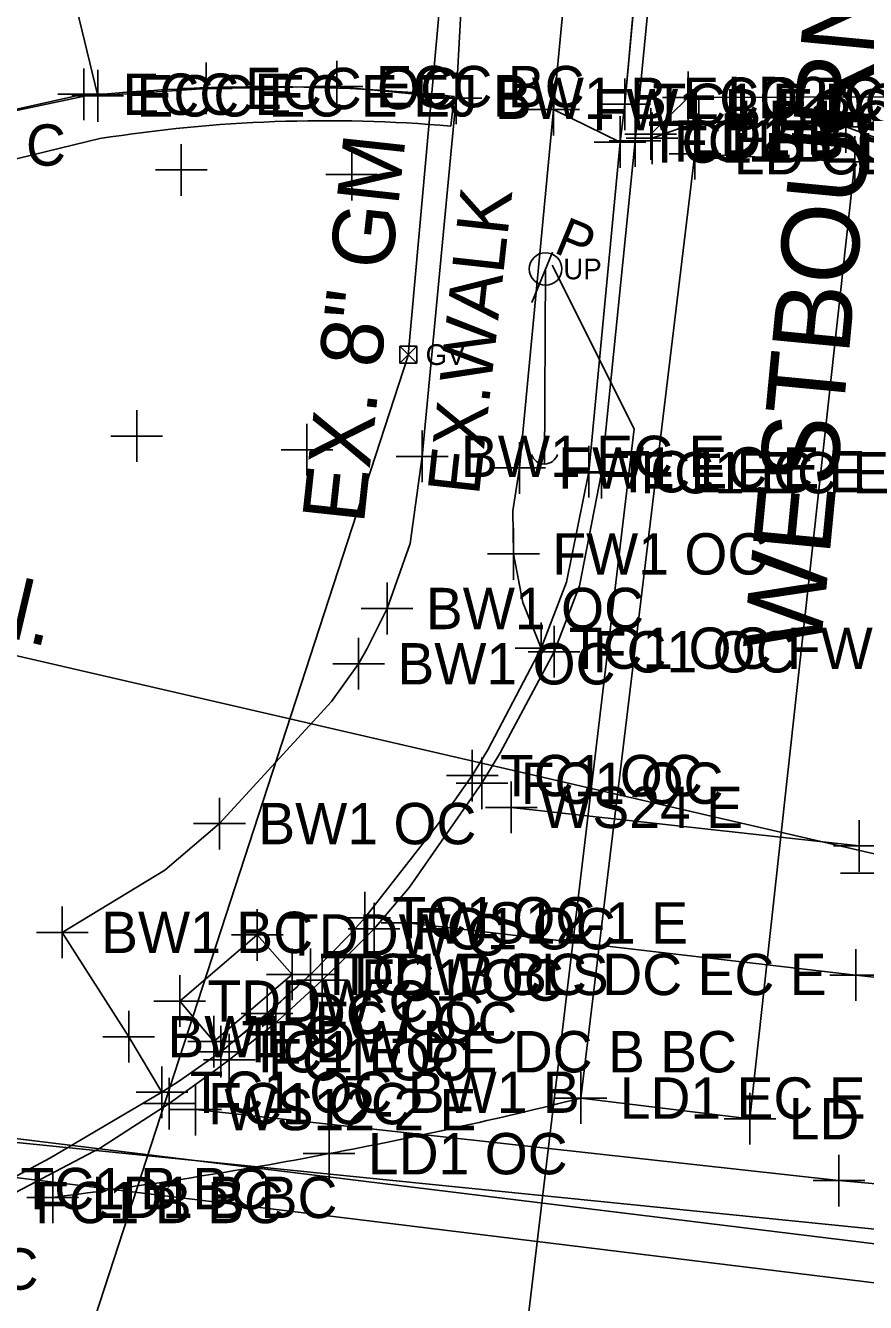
# Model space of a CAD drawing. Extents: x 1363693 to 1365209, y 422201 to 424153.
# Drawn here: x 1364205.52 to 1364238.02, y 423133.99 to 423183.39 of the extents above; entities that cross this region are included whole.
import ezdxf

# ---------------------------------------------------------------- set-up
doc = ezdxf.new("R2010")
doc.units = 0
for name, color, linetype in [('BASELINE-CL-RW', 7, 'Continuous'), ('DR_X_Cells', 7, 'Continuous'), ('DR_X_Storm_Sewer', 7, 'Continuous'), ('O-ALGN-TEXT-BASELINE-WERK-CL-RW', 7, 'Continuous'), ('OWNERS', 7, 'Continuous'), ('PM_X_Channelizing_Line', 7, 'Continuous'), ('PM_X_Crosswalk', 7, 'Continuous'), ('PM_X_Stop_Line', 7, 'Continuous'), ('PV_P_Curb_Ramp', 7, 'Continuous'), ('PV_X_Driveway', 7, 'Continuous'), ('PV_X_Joint', 7, 'Continuous'), ('RD_X_Misc_Items', 7, 'Continuous'), ('RD_X_Text', 7, 'Continuous'), ('SG_X_Wiring', 7, 'Continuous'), ('SV_X_Original_Ground', 7, 'Continuous'), ('SV_X_Shot_Marker', 7, 'Continuous'), ('UT_X_Gas', 7, 'Continuous'), ('UT_X_Gas_Cells', 7, 'Continuous'), ('UT_X_Gas_Text', 7, 'Continuous'), ('UT_X_Misc_Cells', 7, 'Continuous'), ('UT_X_Sanitary_Line', 7, 'Continuous'), ('UT_X_Sanitary_Text', 7, 'Continuous'), ('UT_X_Telecom', 7, 'Continuous'), ('UT_X_Unknown_Cells', 7, 'Continuous'), ('UT_X_Water', 7, 'Continuous')]:
    doc.layers.add(name, color=color, linetype=linetype)

msp = doc.modelspace()

# ---------------------------------------------------------------- linework, layer by layer
at = {"layer": 'BASELINE-CL-RW'}
msp.add_line((1364228.704, 423180.346), (1364229.658, 423190.76), dxfattribs=at)
for points in [[(1364228.704, 423180.346), (1364229.658, 423190.76), (1364230.073, 423195.223)], [(1364216.542, 423146.681), (1364218.062, 423148.207), (1364218.062, 423148.207), (1364218.647, 423148.872), (1364218.647, 423148.872), (1364221.458, 423152.474), (1364221.458, 423152.474), (1364222.808, 423154.374), (1364222.808, 423154.374), (1364223.41, 423155.375), (1364223.41, 423155.375), (1364225.467, 423159.303), (1364225.467, 423159.303), (1364226.448, 423161.853), (1364226.448, 423161.853), (1364227.316, 423166.131), (1364227.316, 423166.131), (1364228.525, 423178.884), (1364228.704, 423180.346)], [(1364213.077, 423143.69), (1364214.869, 423145.175), (1364214.869, 423145.175), (1364216.542, 423146.681), (1364216.542, 423146.681)], [(1364135.44, 423140.481), (1364146.794, 423139.321), (1364171.621, 423136.542), (1364184.9, 423135.157), (1364188.638, 423134.918), (1364188.638, 423134.918), (1364190.871, 423135.022), (1364190.871, 423135.022), (1364195.136, 423135.571), (1364195.136, 423135.571), (1364196.63, 423135.835), (1364196.63, 423135.835), (1364200.837, 423136.985), (1364200.837, 423136.985), (1364204.251, 423138.395), (1364204.251, 423138.395), (1364206.466, 423139.572), (1364206.466, 423139.572), (1364210.799, 423142.123), (1364210.799, 423142.123), (1364211.473, 423142.559), (1364211.473, 423142.559), (1364213.077, 423143.69), (1364213.077, 423143.69)]]:
    msp.add_lwpolyline(points, dxfattribs=at)
for start, end in [(310.84, 313.1458), (308.456, 310.84)]:
    msp.add_arc((1364178.289, 423187.494), 55.937, start, end, dxfattribs=at)
at = {"layer": 'DR_X_Cells'}
msp.add_line((1364225.598, 423166.428), (1364225.641, 423173.976), dxfattribs=at)
at = {"layer": 'DR_X_Storm_Sewer'}
for points in [[(1364396.704, 423122.381), (1364292.466, 423129.632), (1364116.736, 423151.168)], [(1364116.553, 423149.679), (1364292.322, 423128.138), (1364396.6, 423120.885)]]:
    msp.add_lwpolyline(points, dxfattribs=at)
at = {"layer": 'O-ALGN-TEXT-BASELINE-WERK-CL-RW'}
for points in [[(1364225.467, 423159.303), (1364224.762, 423161.077), (1364224.402, 423162.951), (1364224.402, 423162.951), (1364224.38, 423164.624), (1364224.634, 423166.277), (1364224.634, 423166.277), (1364225.951, 423180.141), (1364226.992, 423191.127), (1364227.411, 423195.297), (1364229.35, 423215.953), (1364230.018, 423223.684), (1364231.301, 423237.016), (1364231.57, 423240.495), (1364234.233, 423265.741), (1364235.185, 423277.97)], [(1364210.799, 423142.123), (1364209.512, 423144.272), (1364206.944, 423148.307), (1364210.908, 423150.717), (1364210.908, 423150.717), (1364213.026, 423152.516), (1364213.026, 423152.516), (1364217.363, 423157.247), (1364217.363, 423157.247), (1364218.408, 423158.7), (1364218.408, 423158.7), (1364218.736, 423159.297), (1364218.736, 423159.297), (1364219.511, 423160.839), (1364219.511, 423160.839), (1364220.402, 423163.353), (1364220.402, 423163.353), (1364220.868, 423166.723), (1364220.868, 423166.723), (1364222.181, 423180.581), (1364222.816, 423192.181)]]:
    msp.add_lwpolyline(points, dxfattribs=at)
at = {"layer": 'OWNERS'}
msp.add_line((1364225.951, 423180.141), (1364228.525, 423178.884), dxfattribs=at)
for points in [[(1364204.388, 423137.855), (1364208.419, 423139.966), (1364208.419, 423139.966), (1364211.084, 423141.681), (1364211.084, 423141.681), (1364212.881, 423142.988), (1364212.881, 423142.988), (1364213.403, 423143.382), (1364213.403, 423143.382), (1364214.699, 423144.404), (1364214.699, 423144.404), (1364215.206, 423144.822), (1364215.206, 423144.822), (1364215.65, 423145.214), (1364215.65, 423145.214), (1364217.001, 423146.462), (1364217.001, 423146.462), (1364217.732, 423147.164), (1364217.732, 423147.164), (1364219.01, 423148.449), (1364219.01, 423148.449), (1364220.38, 423150.056), (1364220.38, 423150.056), (1364223.181, 423154.079), (1364223.181, 423154.079), (1364223.885, 423155.254), (1364223.885, 423155.254), (1364225.97, 423159.163), (1364225.97, 423159.163), (1364226.957, 423161.717), (1364226.957, 423161.717), (1364227.81, 423166.094), (1364227.81, 423166.094), (1364229.109, 423178.929), (1364230.246, 423190.614)], [(1364222.181, 423180.581), (1364217.569, 423181.031), (1364212.513, 423180.959), (1364212.513, 423180.959), (1364208.315, 423180.675), (1364208.315, 423180.675)]]:
    msp.add_lwpolyline(points, dxfattribs=at)
at = {"layer": 'PM_X_Channelizing_Line'}
for p, q in [((1364237.781, 423151.651), (1364224.314, 423153.145)), ((1364237.643, 423146.658), (1364220.285, 423148.675)), ((1364248.32, 423145.383), (1364237.643, 423146.658)), ((1364236.991, 423138.704), (1364212.098, 423141.452)), ((1364247.655, 423137.745), (1364236.991, 423138.704))]:
    msp.add_line(p, q, dxfattribs=at)
at = {"layer": 'PM_X_Crosswalk'}
for p, q in [((1364237.643, 423146.658), (1364220.285, 423148.675)), ((1364248.32, 423145.383), (1364237.643, 423146.658)), ((1364236.991, 423138.704), (1364212.098, 423141.452)), ((1364247.655, 423137.745), (1364236.991, 423138.704))]:
    msp.add_line(p, q, dxfattribs=at)
at = {"layer": 'PM_X_Stop_Line'}
msp.add_line((1364237.781, 423151.651), (1364224.314, 423153.145), dxfattribs=at)
at = {"layer": 'PV_P_Curb_Ramp'}
for p, q in [((1364211.486, 423145.647), (1364214.488, 423148.21)), ((1364214.488, 423148.21), (1364215.839, 423146.681)), ((1364215.839, 423146.681), (1364212.802, 423144.082)), ((1364212.802, 423144.082), (1364211.486, 423145.647))]:
    msp.add_line(p, q, dxfattribs=at)
at = {"layer": 'PV_X_Driveway'}
msp.add_line((1364222.101, 423180.652), (1364221.975, 423179.502), dxfattribs=at)
for points in [[(1364222.181, 423180.581), (1364217.569, 423181.031), (1364212.513, 423180.959), (1364212.513, 423180.959), (1364208.315, 423180.675), (1364208.315, 423180.675)], [(1364155.876, 423180.336), (1364161.445, 423179.857), (1364175.888, 423178.423), (1364191.323, 423176.97), (1364200.019, 423179.021), (1364207.804, 423180.664)], [(1364184.767, 423177.698), (1364191.174, 423177.06), (1364198.926, 423178.771), (1364207.772, 423180.738)], [(1364208.394, 423179.018), (1364200.501, 423177.107), (1364191.136, 423174.993)]]:
    msp.add_lwpolyline(points, dxfattribs=at)
for centre, radius, start, end in [((1364214.895, 423111.882), 69.146, 84.01793, 95.88589), ((1364217.146, 423124.207), 55.505, 85.0094, 99.0727)]:
    msp.add_arc(centre, radius, start, end, dxfattribs=at)
at = {"layer": 'PV_X_Joint'}
msp.add_line((1364208.315, 423180.675), (1364206.439, 423188.424), dxfattribs=at)
at = {"layer": 'RD_X_Misc_Items'}
for p, q in [((1364211.486, 423145.647), (1364214.488, 423148.21)), ((1364214.488, 423148.21), (1364215.839, 423146.681)), ((1364215.839, 423146.681), (1364212.802, 423144.082)), ((1364212.802, 423144.082), (1364211.486, 423145.647))]:
    msp.add_line(p, q, dxfattribs=at)
at = {"layer": 'SG_X_Wiring'}
for p, q in [((1364229.712, 423179.192), (1364231.164, 423180.61)), ((1364231.164, 423180.61), (1364243.301, 423180.646)), ((1364229.761, 423179.031), (1364231.57, 423179.684)), ((1364231.57, 423179.684), (1364237.259, 423179.472)), ((1364237.259, 423179.472), (1364243.009, 423177.395)), ((1364231.42, 423178.435), (1364227.013, 423141.896)), ((1364237.607, 423178.115), (1364231.42, 423178.435)), ((1364233.552, 423141.095), (1364237.607, 423178.115)), ((1364227.013, 423141.896), (1364233.552, 423141.095))]:
    msp.add_line(p, q, dxfattribs=at)
for start, end in [(280.78464, 284.09861), (277.18978, 280.78464)]:
    msp.add_arc((1364184.979, 423309.257), 172.559, start, end, dxfattribs=at)
at = {"layer": 'SV_X_Original_Ground'}
for p, q in [((1364231.164, 423179.61), (1364231.164, 423181.61)), ((1364230.164, 423180.61), (1364232.164, 423180.61)), ((1364231.57, 423178.684), (1364231.57, 423180.684)), ((1364237.259, 423178.472), (1364237.259, 423180.472)), ((1364229.712, 423178.192), (1364229.712, 423180.192)), ((1364229.761, 423178.031), (1364229.761, 423180.031)), ((1364230.57, 423179.684), (1364232.57, 423179.684)), ((1364236.259, 423179.472), (1364238.259, 423179.472)), ((1364228.712, 423179.192), (1364230.712, 423179.192)), ((1364228.761, 423179.031), (1364230.761, 423179.031)), ((1364211.548, 423176.807), (1364211.548, 423178.807)), ((1364218.145, 423176.631), (1364218.145, 423178.631)), ((1364210.548, 423177.807), (1364212.548, 423177.807)), ((1364217.145, 423177.631), (1364219.145, 423177.631)), ((1364209.823, 423166.512), (1364209.823, 423168.512)), ((1364216.406, 423165.982), (1364216.406, 423167.982)), ((1364208.823, 423167.512), (1364210.823, 423167.512)), ((1364215.406, 423166.982), (1364217.406, 423166.982)), ((1364224.314, 423152.145), (1364224.314, 423154.145)), ((1364223.314, 423153.145), (1364225.314, 423153.145)), ((1364237.781, 423150.651), (1364237.781, 423152.651)), ((1364236.781, 423151.651), (1364238.781, 423151.651)), ((1364237.05, 423150.599), (1364239.05, 423150.599)), ((1364220.285, 423147.675), (1364220.285, 423149.675)), ((1364214.488, 423147.21), (1364214.488, 423149.21)), ((1364219.285, 423148.675), (1364221.285, 423148.675)), ((1364213.488, 423148.21), (1364215.488, 423148.21)), ((1364215.839, 423145.681), (1364215.839, 423147.681)), ((1364237.643, 423145.658), (1364237.643, 423147.658)), ((1364211.486, 423144.647), (1364211.486, 423146.647)), ((1364214.839, 423146.681), (1364216.839, 423146.681)), ((1364236.643, 423146.658), (1364238.643, 423146.658)), ((1364210.486, 423145.647), (1364212.486, 423145.647)), ((1364212.802, 423143.082), (1364212.802, 423145.082)), ((1364211.802, 423144.082), (1364213.802, 423144.082)), ((1364212.098, 423140.452), (1364212.098, 423142.452)), ((1364227.013, 423140.896), (1364227.013, 423142.896)), ((1364211.098, 423141.452), (1364213.098, 423141.452)), ((1364226.013, 423141.896), (1364228.013, 423141.896)), ((1364217.268, 423138.746), (1364217.268, 423140.746)), ((1364216.268, 423139.746), (1364218.268, 423139.746)), ((1364236.991, 423137.704), (1364236.991, 423139.704)), ((1364206.576, 423137.055), (1364206.576, 423139.055)), ((1364235.991, 423138.704), (1364237.991, 423138.704)), ((1364205.576, 423138.055), (1364207.576, 423138.055))]:
    msp.add_line(p, q, dxfattribs=at)
at = {"layer": 'SV_X_Shot_Marker'}
for p, q in [((1364212.513, 423179.959), (1364212.513, 423181.959)), ((1364217.569, 423180.031), (1364217.569, 423182.031)), ((1364207.772, 423179.738), (1364207.772, 423181.738)), ((1364208.315, 423179.675), (1364208.315, 423181.675)), ((1364222.181, 423179.581), (1364222.181, 423181.581)), ((1364211.513, 423180.959), (1364213.513, 423180.959)), ((1364216.569, 423181.031), (1364218.569, 423181.031)), ((1364225.951, 423179.141), (1364225.951, 423181.141)), ((1364228.704, 423179.346), (1364228.704, 423181.346)), ((1364206.772, 423180.738), (1364208.772, 423180.738)), ((1364207.315, 423180.675), (1364209.315, 423180.675)), ((1364221.181, 423180.581), (1364223.181, 423180.581)), ((1364224.951, 423180.141), (1364226.951, 423180.141)), ((1364227.704, 423180.346), (1364229.704, 423180.346)), ((1364228.525, 423177.884), (1364228.525, 423179.884)), ((1364229.109, 423177.929), (1364229.109, 423179.929)), ((1364231.42, 423177.435), (1364231.42, 423179.435)), ((1364237.607, 423177.115), (1364237.607, 423179.115)), ((1364227.525, 423178.884), (1364229.525, 423178.884)), ((1364228.109, 423178.929), (1364230.109, 423178.929)), ((1364230.42, 423178.435), (1364232.42, 423178.435)), ((1364236.607, 423178.115), (1364238.607, 423178.115)), ((1364220.868, 423165.723), (1364220.868, 423167.723)), ((1364224.634, 423165.277), (1364224.634, 423167.277)), ((1364227.316, 423165.131), (1364227.316, 423167.131)), ((1364219.868, 423166.723), (1364221.868, 423166.723)), ((1364227.81, 423165.094), (1364227.81, 423167.094)), ((1364223.634, 423166.277), (1364225.634, 423166.277)), ((1364226.316, 423166.131), (1364228.316, 423166.131)), ((1364226.81, 423166.094), (1364228.81, 423166.094)), ((1364224.402, 423161.951), (1364224.402, 423163.951)), ((1364223.402, 423162.951), (1364225.402, 423162.951)), ((1364219.511, 423159.839), (1364219.511, 423161.839)), ((1364218.511, 423160.839), (1364220.511, 423160.839)), ((1364225.467, 423158.303), (1364225.467, 423160.303)), ((1364225.97, 423158.163), (1364225.97, 423160.163)), ((1364218.408, 423157.7), (1364218.408, 423159.7)), ((1364224.467, 423159.303), (1364226.467, 423159.303)), ((1364224.97, 423159.163), (1364226.97, 423159.163)), ((1364217.408, 423158.7), (1364219.408, 423158.7)), ((1364222.808, 423153.374), (1364222.808, 423155.374)), ((1364223.181, 423153.079), (1364223.181, 423155.079)), ((1364221.808, 423154.374), (1364223.808, 423154.374)), ((1364222.181, 423154.079), (1364224.181, 423154.079)), ((1364213.026, 423151.516), (1364213.026, 423153.516)), ((1364212.026, 423152.516), (1364214.026, 423152.516)), ((1364218.647, 423147.872), (1364218.647, 423149.872)), ((1364219.01, 423147.449), (1364219.01, 423149.449)), ((1364206.944, 423147.307), (1364206.944, 423149.307)), ((1364217.647, 423148.872), (1364219.647, 423148.872)), ((1364218.01, 423148.449), (1364220.01, 423148.449)), ((1364205.944, 423148.307), (1364207.944, 423148.307)), ((1364216.542, 423145.681), (1364216.542, 423147.681)), ((1364217.001, 423145.462), (1364217.001, 423147.462)), ((1364215.542, 423146.681), (1364217.542, 423146.681)), ((1364216.001, 423146.462), (1364218.001, 423146.462)), ((1364214.869, 423144.175), (1364214.869, 423146.175)), ((1364215.206, 423143.822), (1364215.206, 423145.822)), ((1364209.512, 423143.272), (1364209.512, 423145.272)), ((1364213.869, 423145.175), (1364215.869, 423145.175)), ((1364213.077, 423142.69), (1364213.077, 423144.69)), ((1364214.206, 423144.822), (1364216.206, 423144.822)), ((1364208.512, 423144.272), (1364210.512, 423144.272)), ((1364213.403, 423142.382), (1364213.403, 423144.382)), ((1364212.077, 423143.69), (1364214.077, 423143.69)), ((1364210.799, 423141.123), (1364210.799, 423143.123)), ((1364212.403, 423143.382), (1364214.403, 423143.382)), ((1364211.084, 423140.681), (1364211.084, 423142.681)), ((1364209.799, 423142.123), (1364211.799, 423142.123)), ((1364233.552, 423140.095), (1364233.552, 423142.095)), ((1364210.084, 423141.681), (1364212.084, 423141.681)), ((1364232.552, 423141.095), (1364234.552, 423141.095))]:
    msp.add_line(p, q, dxfattribs=at)
at = {"layer": 'UT_X_Gas'}
msp.add_lwpolyline([(1364194.448, 423091.209), (1364220.328, 423170.624), (1364225.475, 423227.742)], dxfattribs=at)
at = {"layer": 'UT_X_Gas_Cells'}
for p, q in [((1364219.999, 423170.328), (1364220.664, 423170.993)), ((1364219.999, 423170.993), (1364220.664, 423170.328)), ((1364219.999, 423170.993), (1364220.664, 423170.993)), ((1364219.999, 423170.328), (1364219.999, 423170.993)), ((1364220.664, 423170.328), (1364220.664, 423170.993)), ((1364219.999, 423170.328), (1364220.664, 423170.328))]:
    msp.add_line(p, q, dxfattribs=at)
at = {"layer": 'UT_X_Sanitary_Line'}
msp.add_lwpolyline([(1364693.403, 423102.755), (1364519.502, 423118.915), (1364254.219, 423147.686), (1364120.797, 423178.489), (1364080.299, 423181.531), (1364078.775, 423157.716), (1364068.834, 423074.38), (1364132.412, 423042.257), (1364111.643, 422924.766), (1364032.031, 422957.358)], dxfattribs=at)
at = {"layer": 'UT_X_Telecom'}
for p, q in [((1364225.897, 423174.119), (1364229.066, 423167.793)), ((1364229.066, 423167.793), (1364220.065, 423092.139))]:
    msp.add_line(p, q, dxfattribs=at)
at = {"layer": 'UT_X_Unknown_Cells'}
for p, q in [((1364225.107, 423172.682), (1364225.91, 423174.627)), ((1364225.598, 423166.428), (1364225.641, 423173.976))]:
    msp.add_line(p, q, dxfattribs=at)
msp.add_circle((1364225.641, 423173.976), 0.63, dxfattribs=at)
msp.add_arc((1364225.603, 423166.95), 0.522, 196.725, 343.6589, dxfattribs=at)
at = {"layer": 'UT_X_Water'}
msp.add_lwpolyline([(1364199.274, 423140.77), (1364264.462, 423134.201), (1364302.919, 423131.268), (1364302.919, 423124.149), (1364488.328, 423104.035), (1364526.667, 423100.332), (1364656.437, 423088.194), (1364694.224, 423084.44)], dxfattribs=at)

# ---------------------------------------------------------------- texts
at = {"layer": 'RD_X_Text'}
for s, height, rotation, p in [('WESTBOURNE ROAD', 3, 84.5334, (1364236.268, 423159.076)), ('EX.WALK', 2, 83.7177, (1364223.061, 423165.173))]:
    msp.add_text(s, height=height, rotation=rotation, dxfattribs=at).set_placement(p)
at = {"layer": 'SV_X_Original_Ground'}
for s, p in [('LD2 C', (1364232.664, 423179.81)), ('LD1 C', (1364233.07, 423178.884)), ('LD2 B', (1364231.212, 423178.392)), ('LD1 B', (1364231.261, 423178.231)), ('WS24 E', (1364225.433, 423152.345)), ('WS12-1 E', (1364221.404, 423147.875)), ('TDDW C', (1364215.559, 423147.41)), ('TDDW CLS', (1364216.91, 423145.881)), ('TDDW C', (1364212.557, 423144.847)), ('TDDW B', (1364213.873, 423143.282)), ('LD1 EC E LD B', (1364228.513, 423141.096)), ('WS12-2 E', (1364213.217, 423140.652)), ('LD1 OC', (1364218.768, 423138.946)), ('LD1 B BC', (1364208.076, 423137.255))]:
    msp.add_text(s, height=1.6, dxfattribs=at).set_placement(p)
at = {"layer": 'SV_X_Shot_Marker'}
for s, p in [('ECC E', (1364209.272, 423179.938)), ('ECC EC E EJ B', (1364209.815, 423179.875)), ('ECC OC', (1364214.013, 423180.159)), ('ECC BC', (1364219.069, 423180.231)), ('BW1 B ECC B', (1364223.681, 423179.781)), ('FW1 B ECC B', (1364227.451, 423179.341)), ('TC1 E DC B', (1364229.775, 423179.546)), ('ECC C', (1364200.426, 423177.971)), ('TC1 B ECC E', (1364229.596, 423178.084)), ('FC1 B', (1364230.609, 423178.129)), ('LD CLS', (1364232.92, 423177.635)), ('BW1 EC E', (1364222.368, 423165.923)), ('FW1 EC E', (1364226.134, 423165.477)), ('TC1 EC E', (1364228.387, 423165.331)), ('FC1 EC E', (1364229.31, 423165.294)), ('FW1 OC', (1364225.902, 423162.151)), ('BW1 OC', (1364221.011, 423160.039)), ('TC1 OC FW1 B BC', (1364226.538, 423158.503)), ('FC1 OC', (1364227.47, 423158.363)), ('BW1 OC', (1364219.908, 423157.9)), ('TC1 OC', (1364223.879, 423153.574)), ('FC1 OC', (1364224.681, 423153.279)), ('BW1 OC', (1364214.526, 423151.716)), ('TC1 OC', (1364219.718, 423148.072)), ('BW1 BC', (1364208.444, 423147.507)), ('FC1 OC', (1364220.51, 423147.649)), ('TC1 B BC DC EC E', (1364217.613, 423145.881)), ('FC1 OC', (1364218.501, 423145.662)), ('DC OC', (1364216.369, 423144.375)), ('FC1 OC', (1364216.706, 423144.022)), ('BW1 C', (1364211.012, 423143.472)), ('TC1 EC E DC B BC', (1364214.148, 423142.89)), ('FC1 OC', (1364214.903, 423142.582)), ('TC1 OC BW1 B', (1364211.87, 423141.323)), ('FC1 OC', (1364212.584, 423140.881)), ('LD C', (1364235.052, 423140.295)), ('TC1 B BC', (1364205.322, 423137.595)), ('FC1 B BC', (1364205.888, 423137.055)), ('FC1 OC', (1364198.178, 423134.483))]:
    msp.add_text(s, height=1.6, dxfattribs=at).set_placement(p)
at = {"layer": 'UT_X_Gas_Text'}
msp.add_text('EX. 8" GM', height=2.4, rotation=83.8091, dxfattribs=at).set_placement((1364218.606, 423164.07))
msp.add_text('GV', height=0.8, dxfattribs=at).set_placement((1364221, 423170.261))
at = {"layer": 'UT_X_Misc_Cells'}
msp.add_text('UP', height=0.8, dxfattribs=at).set_placement((1364226.33, 423173.576))
at = {"layer": 'UT_X_Sanitary_Text'}
msp.add_text('EX. 12" SAN.', height=2.4, rotation=346.7222, dxfattribs=at).set_placement((1364187.759, 423163.755))
at = {"layer": 'UT_X_Unknown_Cells'}
msp.add_text('P', height=1.503, rotation=337.5827, dxfattribs=at).set_placement((1364225.91, 423174.627))

doc.saveas('drawing.dxf')
